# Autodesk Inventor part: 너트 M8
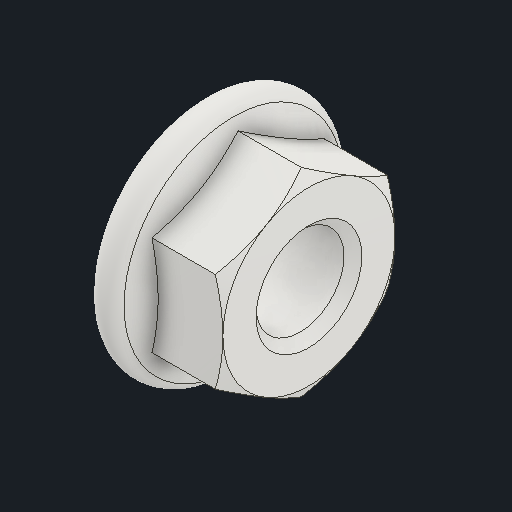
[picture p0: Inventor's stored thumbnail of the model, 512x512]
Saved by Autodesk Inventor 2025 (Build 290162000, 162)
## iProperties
Created: 2025-08
Part Number: 너트 M8
Material: 스테인리스강
Description: 플랜지붙이 6각 너트 - 일반 스레드
Document SubType Name: Modeling
Designer: infra005
Density: 8 g/cm^3
Appearance: 기본값
Author: jhkim
Sending System: Autodesk Inventor 2026
Preprocessor: ST-DEVELOPER v20.1
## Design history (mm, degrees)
feature "Solid1"
node "솔리드1"
